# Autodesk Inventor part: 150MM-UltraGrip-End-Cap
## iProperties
Created: 2012-04
Part Number: 150MM-UltraGrip-End-Cap
Document SubType Name: Modeling
Designer: D Cole
Density: 1 g/cm^3
Author: D Cole
